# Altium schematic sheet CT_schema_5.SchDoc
size 251 x 159 mm
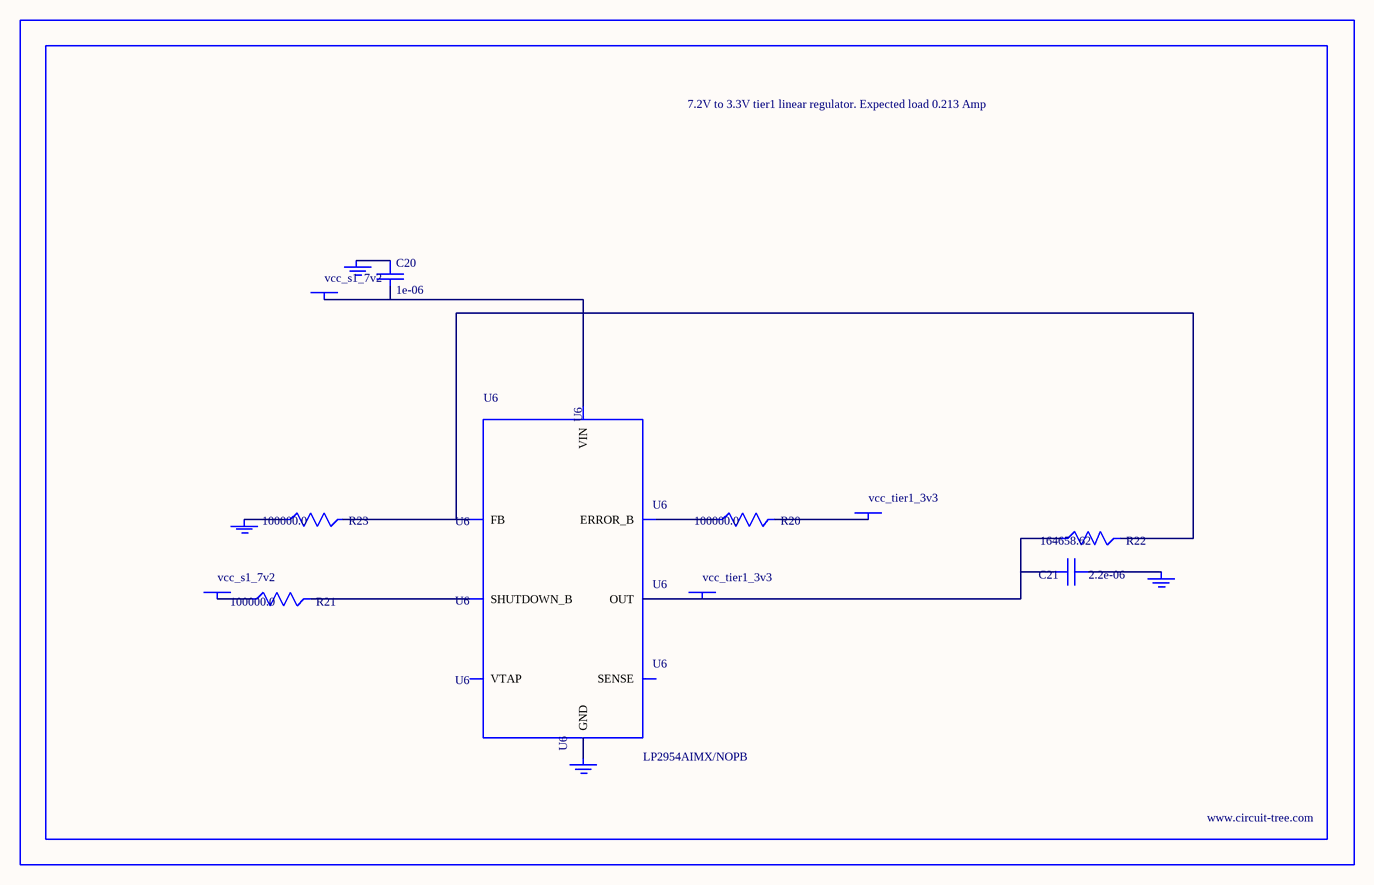
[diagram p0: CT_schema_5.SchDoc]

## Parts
BORDER4  (no value)
C20  1e-06  [EXV-9B]
C21  2.2e-06  [EXV-9B]
GND_INSTANCE_4_0  (no value)
GND_INSTANCE_4_1  (no value)
GND_INSTANCE_4_2  (no value)
GND_INSTANCE_4_3  (no value)
POWER_INSTANCE_4_0  vcc_s1_7v2
POWER_INSTANCE_4_1  vcc_tier1_3v3
POWER_INSTANCE_4_2  vcc_s1_7v2
POWER_INSTANCE_4_3  vcc_tier1_3v3
R20  100000.0  [R0603]
R21  100000.0  [R0603]
R22  164658.62  [R0603]
R23  100000.0  [R0603]
U6  LP2954AIMX/NOPB  [LP2954]

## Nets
NetC20_1: C20.1 GND_INSTANCE_4_2.0(GND)
NetC20_2: C20.2 POWER_INSTANCE_4_2.0(PWR) U6.8(VIN)
NetC21_1: C21.1 GND_INSTANCE_4_0.0(GND)
NetC21_2: C21.2 POWER_INSTANCE_4_3.0(PWR) R22.1 U6.1(OUT)
NetGND_INSTANCE_4_1_0: GND_INSTANCE_4_1.0(GND) R23.1
NetGND_INSTANCE_4_3_0: GND_INSTANCE_4_3.0(GND) U6.4(GND)
NetPOWER_INSTANCE_4_0_0: POWER_INSTANCE_4_0.0(PWR) R21.1
NetPOWER_INSTANCE_4_1_0: POWER_INSTANCE_4_1.0(PWR) R20.2
NetR20_1: R20.1 U6.5(ERROR_B)
NetR21_2: R21.2 U6.3(SHUTDOWN_B)
NetR22_2: R22.2 R23.2 U6.7(FB)

Not connected (* = marked no-connect by the designer): U6 2(SENSE) 6(VTAP)

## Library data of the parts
BORDER4 = BORDER_PAGE4
C20 = EDK105M050A9BAA
C21 = EDK225M050A9BAA
GND_INSTANCE_4_0-GND_INSTANCE_4_3 = GND
POWER_INSTANCE_4_0-POWER_INSTANCE_4_3 = PWR
R20 R21 R23 = RC0603JR-07100KL
R22 = R22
